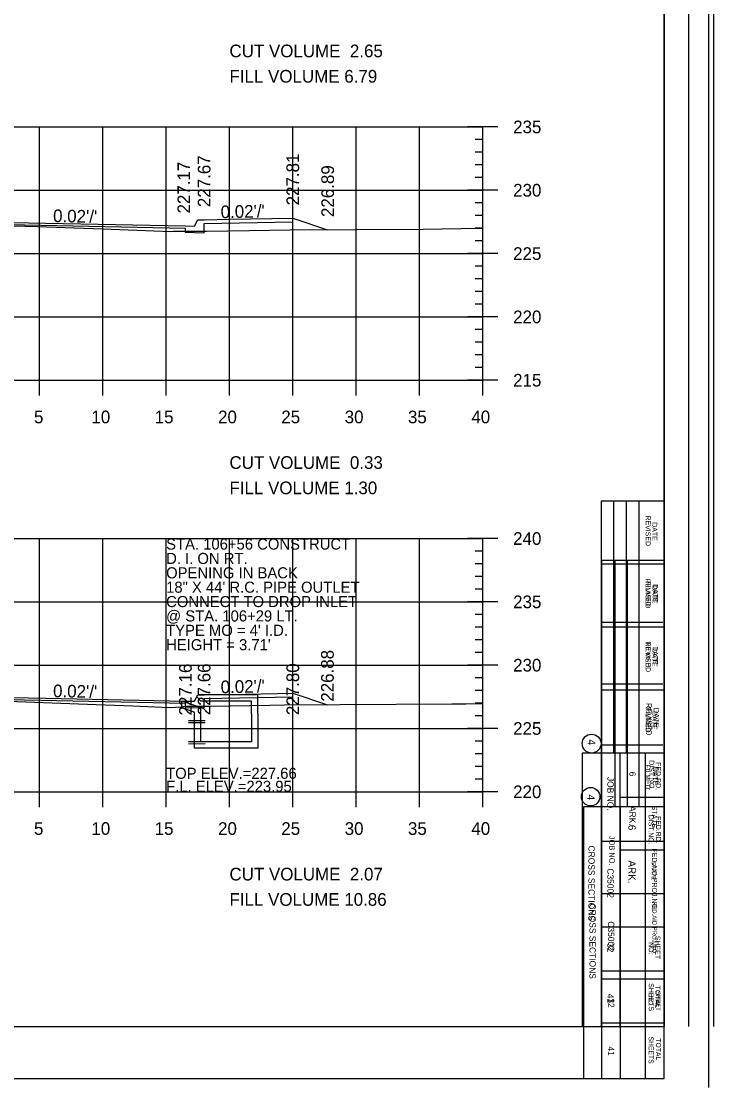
# Model space of a CAD drawing. Extents: x 1367903 to 1373764, y 376865 to 382130.
# Drawn here: x 1371513.6 to 1371623, y 377279.1 to 377447.5 of the extents above; entities that cross this region are included whole.
import ezdxf

# ---------------------------------------------------------------- set-up
doc = ezdxf.new("R2010")
doc.units = 0
for name, color, linetype in [('R_Axis', 7, 'Continuous'), ('R_Axis Annot', 7, 'Continuous'), ('R_Border', 7, 'Continuous'), ('R_Border Notes', 7, 'Continuous'), ('R_Border PE', 7, 'Continuous'), ('R_Draft', 7, 'Continuous'), ('R_Exist Surface', 7, 'Continuous'), ('R_Fin Surface', 7, 'Continuous'), ('R_Fin Surface Annot', 7, 'Continuous'), ('R_Grid', 7, 'Continuous'), ('R_Water', 7, 'Continuous'), ('R_Water Annot', 7, 'Continuous')]:
    doc.layers.add(name, color=color, linetype=linetype)

msp = doc.modelspace()

# ---------------------------------------------------------------- linework, layer by layer
for p, q in [((1371539.01, 377340.19), (1371542.01, 377339.15)), ((1371541.35, 377340.82), (1371541.51, 377341.15)), ((1371541.35, 377340.82), (1371542.01, 377340.15)), ((1371551.01, 377341.15), (1371541.51, 377341.15)), ((1371550.01, 377340.15), (1371542.01, 377340.15)), ((1371550.01, 377338.15), (1371550.01, 377340.15)), ((1371551.01, 377338.15), (1371551.01, 377341.15)), ((1371539.01, 377339.13), (1371541.01, 377338.43)), ((1371541.01, 377338.15), (1371541.01, 377338.43)), ((1371542.01, 377338.15), (1371542.01, 377339.15))]:
    msp.add_line(p, q)
for points in [[(1371470.51, 377416.17), (1371470.51, 377415.5), (1371470.51, 377415.5), (1371470.51, 377414.14), (1371473.51, 377414.2), (1371473.51, 377414.87), (1371506.51, 377415.53), (1371539.51, 377414.87), (1371539.51, 377414.2), (1371542.51, 377414.14), (1371542.51, 377415.58), (1371556.51, 377415.86), (1371556.51, 377416.45)], [(1371470.51, 377341.15), (1371470.51, 377340.48), (1371470.51, 377340.48), (1371470.51, 377339.12), (1371473.51, 377339.18), (1371473.51, 377339.84), (1371506.51, 377340.5), (1371539.51, 377339.84), (1371539.51, 377339.18), (1371542.51, 377339.12), (1371542.51, 377340.56), (1371556.51, 377340.84), (1371556.51, 377341.43)], [(1371539.01, 377339.13), (1371539.01, 377340.19)]]:
    msp.add_lwpolyline(points)
at = {"layer": 'R_Axis'}
for p, q in [((1371588.91, 377430.84), (1371584.11, 377430.84)), ((1371586.51, 377390.84), (1371586.51, 377430.84)), ((1371586.51, 377428.84), (1371585.31, 377428.84)), ((1371586.51, 377426.84), (1371585.31, 377426.84)), ((1371586.51, 377424.84), (1371585.31, 377424.84)), ((1371586.51, 377422.84), (1371585.31, 377422.84)), ((1371588.91, 377420.84), (1371584.11, 377420.84)), ((1371586.51, 377418.84), (1371585.31, 377418.84)), ((1371586.51, 377416.84), (1371585.31, 377416.84)), ((1371586.51, 377414.84), (1371585.31, 377414.84)), ((1371586.51, 377412.84), (1371585.31, 377412.84)), ((1371588.91, 377410.84), (1371584.11, 377410.84)), ((1371586.51, 377408.84), (1371585.31, 377408.84)), ((1371586.51, 377406.84), (1371585.31, 377406.84)), ((1371586.51, 377404.84), (1371585.31, 377404.84)), ((1371586.51, 377402.84), (1371585.31, 377402.84)), ((1371588.91, 377400.84), (1371584.11, 377400.84)), ((1371586.51, 377398.84), (1371585.31, 377398.84)), ((1371586.51, 377396.84), (1371585.31, 377396.84)), ((1371586.51, 377394.84), (1371585.31, 377394.84)), ((1371516.51, 377388.44), (1371516.51, 377393.24)), ((1371526.51, 377388.44), (1371526.51, 377393.24)), ((1371536.51, 377388.44), (1371536.51, 377393.24)), ((1371546.51, 377388.44), (1371546.51, 377393.24)), ((1371556.51, 377388.44), (1371556.51, 377393.24)), ((1371566.51, 377388.44), (1371566.51, 377393.24)), ((1371576.51, 377388.44), (1371576.51, 377393.24)), ((1371586.51, 377392.84), (1371585.31, 377392.84)), ((1371586.51, 377388.44), (1371586.51, 377393.24)), ((1371426.51, 377390.84), (1371586.51, 377390.84)), ((1371588.91, 377390.84), (1371584.11, 377390.84)), ((1371588.91, 377365.84), (1371584.11, 377365.84)), ((1371586.51, 377325.84), (1371586.51, 377365.84)), ((1371586.51, 377363.84), (1371585.31, 377363.84)), ((1371586.51, 377361.84), (1371585.31, 377361.84)), ((1371586.51, 377359.84), (1371585.31, 377359.84)), ((1371586.51, 377357.84), (1371585.31, 377357.84)), ((1371588.91, 377355.84), (1371584.11, 377355.84)), ((1371586.51, 377353.84), (1371585.31, 377353.84)), ((1371586.51, 377351.84), (1371585.31, 377351.84)), ((1371586.51, 377349.84), (1371585.31, 377349.84)), ((1371586.51, 377347.84), (1371585.31, 377347.84)), ((1371588.91, 377345.84), (1371584.11, 377345.84)), ((1371586.51, 377343.84), (1371585.31, 377343.84)), ((1371586.51, 377341.84), (1371585.31, 377341.84)), ((1371586.51, 377339.84), (1371585.31, 377339.84)), ((1371586.51, 377337.84), (1371585.31, 377337.84)), ((1371588.91, 377335.84), (1371584.11, 377335.84)), ((1371586.51, 377333.84), (1371585.31, 377333.84)), ((1371586.51, 377331.84), (1371585.31, 377331.84)), ((1371586.51, 377329.84), (1371585.31, 377329.84)), ((1371516.51, 377323.44), (1371516.51, 377328.24)), ((1371526.51, 377323.44), (1371526.51, 377328.24)), ((1371536.51, 377323.44), (1371536.51, 377328.24)), ((1371546.51, 377323.44), (1371546.51, 377328.24)), ((1371556.51, 377323.44), (1371556.51, 377328.24)), ((1371566.51, 377323.44), (1371566.51, 377328.24)), ((1371576.51, 377323.44), (1371576.51, 377328.24)), ((1371586.51, 377323.44), (1371586.51, 377328.24)), ((1371586.51, 377327.84), (1371585.31, 377327.84)), ((1371426.51, 377325.84), (1371586.51, 377325.84)), ((1371588.91, 377325.84), (1371584.11, 377325.84))]:
    msp.add_line(p, q, dxfattribs=at)
at = {"layer": 'R_Border'}
for p, q in [((1371622.18, 377620.35), (1371622.18, 377279.12)), ((1371615.14, 377280.59), (1371615.14, 377611.47)), ((1371615.14, 377446.03), (1371615.14, 377446.03)), ((1371605.33, 377280.59), (1371605.33, 377362.43)), ((1371605.33, 377362.43), (1371615.14, 377362.43)), ((1371605.33, 377362.43), (1371607.36, 377362.43)), ((1371607.36, 377362.43), (1371607.36, 377323.46)), ((1371609.31, 377362.43), (1371609.31, 377323.46)), ((1371611.16, 377362.43), (1371611.16, 377323.46)), ((1371605.33, 377352.62), (1371614.94, 377352.62)), ((1371605.33, 377342.9), (1371614.94, 377342.9)), ((1371605.33, 377333.27), (1371614.94, 377333.27)), ((1371615.14, 377323.46), (1371602.41, 377323.46)), ((1371602.41, 377323.46), (1371602.41, 377280.59)), ((1371608.24, 377280.59), (1371608.24, 377323.46)), ((1371612.22, 377280.59), (1371612.22, 377323.46)), ((1371615.14, 377316.65), (1371608.24, 377316.65)), ((1371615.14, 377309.75), (1371605.33, 377309.75)), ((1371615.14, 377296.24), (1371605.33, 377296.24)), ((1371615.14, 377289.33), (1371605.33, 377289.33)), ((1371410.82, 377280.59), (1371615.14, 377280.59))]:
    msp.add_line(p, q, dxfattribs=at)
msp.add_circle((1371603.55, 377325.07), 1.46, dxfattribs=at)
at = {"layer": 'R_Border PE'}
for p, q in [((1371619.06, 377288.8), (1371619.06, 377610.76)), ((1371622.98, 377288.8), (1371622.98, 377610.76)), ((1371615.14, 377603.25), (1371615.14, 377288.8)), ((1371605.19, 377371.74), (1371605.19, 377288.8)), ((1371615.14, 377371.74), (1371605.19, 377371.74)), ((1371607.18, 377371.74), (1371607.18, 377331.96)), ((1371609.17, 377371.74), (1371609.17, 377331.96)), ((1371611.16, 377371.74), (1371611.16, 377331.96)), ((1371615.14, 377361.8), (1371605.19, 377361.8)), ((1371615.14, 377351.85), (1371605.19, 377351.85)), ((1371615.14, 377341.91), (1371605.19, 377341.91)), ((1371615.14, 377331.96), (1371602.21, 377331.96)), ((1371602.21, 377331.96), (1371602.21, 377288.8)), ((1371608.18, 377331.96), (1371608.18, 377288.8)), ((1371612.15, 377331.96), (1371612.15, 377288.8)), ((1371608.24, 377325), (1371615.14, 377325)), ((1371605.32, 377318.04), (1371615.14, 377318.04)), ((1371605.32, 377304.51), (1371615.14, 377304.51)), ((1371605.32, 377297.55), (1371615.14, 377297.55)), ((1371410.82, 377288.8), (1371615.14, 377288.8)), ((1371612.25, 377288.8), (1371612.25, 377288.8))]:
    msp.add_line(p, q, dxfattribs=at)
msp.add_circle((1371603.7, 377333.45), 1.49, dxfattribs=at)
at = {"layer": 'R_Exist Surface'}
for points in [[(1371506.64, 377415.36), (1371516.16, 377415.09), (1371522, 377414.89), (1371526.44, 377414.73), (1371531.88, 377414.53), (1371537.27, 377414.34), (1371537.62, 377414.37), (1371539.93, 377414.36), (1371542.88, 377414.37), (1371549.6, 377414.49), (1371556.1, 377414.58), (1371577.12, 377414.7), (1371586.07, 377414.85), (1371586.51, 377414.85)], [(1371508.7, 377340.26), (1371525.47, 377339.64), (1371531.23, 377339.43), (1371537.06, 377339.18), (1371538.95, 377339.28), (1371539.54, 377339.36), (1371541.84, 377339.35), (1371543.45, 377339.36), (1371552.9, 377339.53), (1371555.19, 377339.57), (1371581.63, 377339.72), (1371583.86, 377339.75), (1371586.51, 377339.77)]]:
    msp.add_lwpolyline(points, dxfattribs=at)
at = {"layer": 'R_Fin Surface'}
for points in [[(1371467.84, 377415.28), (1371470.51, 377416.17), (1371471.51, 377416.17), (1371472.01, 377415.17), (1371473.51, 377415.2), (1371495.51, 377415.64), (1371506.51, 377415.86), (1371517.51, 377415.64), (1371539.51, 377415.2), (1371541.01, 377415.17), (1371541.51, 377416.17), (1371542.51, 377416.17), (1371546.51, 377416.25), (1371556.51, 377416.45), (1371562.02, 377414.61)], [(1371467.79, 377340.24), (1371470.51, 377341.15), (1371471.51, 377341.15), (1371472.01, 377340.15), (1371473.51, 377340.18), (1371495.51, 377340.62), (1371506.51, 377340.84), (1371517.51, 377340.62), (1371539.51, 377340.18), (1371541.01, 377340.15), (1371541.51, 377341.15), (1371542.51, 377341.15), (1371546.51, 377341.23), (1371556.51, 377341.43), (1371561.98, 377339.6)]]:
    msp.add_lwpolyline(points, dxfattribs=at)
at = {"layer": 'R_Grid'}
for p, q in [((1371426.51, 377430.84), (1371586.51, 377430.84)), ((1371516.51, 377390.84), (1371516.51, 377430.84)), ((1371526.51, 377390.84), (1371526.51, 377430.84)), ((1371536.51, 377390.84), (1371536.51, 377430.84)), ((1371546.51, 377390.84), (1371546.51, 377430.84)), ((1371556.51, 377390.84), (1371556.51, 377430.84)), ((1371566.51, 377390.84), (1371566.51, 377430.84)), ((1371576.51, 377390.84), (1371576.51, 377430.84)), ((1371586.51, 377390.84), (1371586.51, 377430.84)), ((1371426.51, 377420.84), (1371586.51, 377420.84)), ((1371426.51, 377410.84), (1371586.51, 377410.84)), ((1371426.51, 377400.84), (1371586.51, 377400.84)), ((1371426.51, 377390.84), (1371586.51, 377390.84)), ((1371426.51, 377365.84), (1371586.51, 377365.84)), ((1371516.51, 377325.84), (1371516.51, 377365.84)), ((1371526.51, 377325.84), (1371526.51, 377365.84)), ((1371536.51, 377325.84), (1371536.51, 377365.84)), ((1371546.51, 377325.84), (1371546.51, 377365.84)), ((1371556.51, 377325.84), (1371556.51, 377365.84)), ((1371566.51, 377325.84), (1371566.51, 377365.84)), ((1371576.51, 377325.84), (1371576.51, 377365.84)), ((1371586.51, 377325.84), (1371586.51, 377365.84)), ((1371426.51, 377355.84), (1371586.51, 377355.84)), ((1371426.51, 377345.84), (1371586.51, 377345.84)), ((1371426.51, 377335.84), (1371586.51, 377335.84)), ((1371426.51, 377325.84), (1371586.51, 377325.84))]:
    msp.add_line(p, q, dxfattribs=at)
at = {"layer": 'R_Water'}
for p, q in [((1371542.69, 377337.07), (1371540.04, 377337.05)), ((1371542.69, 377336.74), (1371540.04, 377336.72)), ((1371542.69, 377333.74), (1371540.04, 377333.72)), ((1371542.69, 377333.4), (1371540.04, 377333.39))]:
    msp.add_line(p, q, dxfattribs=at)
for points in [[(1371551.01, 377338.15), (1371551.01, 377332.74), (1371546.01, 377332.74), (1371541.01, 377332.74), (1371541.01, 377338.15)], [(1371550.01, 377338.15), (1371550.01, 377333.74), (1371546.01, 377333.74), (1371542.01, 377333.74), (1371542.01, 377338.15)]]:
    msp.add_lwpolyline(points, dxfattribs=at)

# ---------------------------------------------------------------- texts
at = {"layer": 'R_Axis Annot'}
for s, p in [('CUT VOLUME  2.65', (1371546.51, 377441.84)), ('FILL VOLUME 6.79', (1371546.51, 377437.84)), ('235', (1371591.31, 377429.84)), ('230', (1371591.31, 377419.84)), ('225', (1371591.31, 377409.84)), ('220', (1371591.31, 377399.84)), ('215', (1371591.31, 377389.84)), ('5', (1371515.64, 377384.04)), ('10', (1371524.71, 377384.04)), ('15', (1371534.7, 377384.04)), ('20', (1371544.71, 377384.04)), ('25', (1371554.7, 377384.04)), ('30', (1371564.71, 377384.04)), ('35', (1371574.7, 377384.04)), ('40', (1371584.71, 377384.04)), ('CUT VOLUME  0.33', (1371546.51, 377376.84)), ('FILL VOLUME 1.30', (1371546.51, 377372.84)), ('240', (1371591.31, 377364.84)), ('235', (1371591.31, 377354.84)), ('230', (1371591.31, 377344.84)), ('225', (1371591.31, 377334.84)), ('220', (1371591.31, 377324.84)), ('5', (1371515.64, 377319.04)), ('10', (1371524.71, 377319.04)), ('15', (1371534.7, 377319.04)), ('20', (1371544.71, 377319.04)), ('25', (1371554.7, 377319.04)), ('30', (1371564.71, 377319.04)), ('35', (1371574.7, 377319.04)), ('40', (1371584.71, 377319.04)), ('CUT VOLUME  2.07', (1371546.51, 377311.84)), ('FILL VOLUME 10.86', (1371546.51, 377307.84))]:
    msp.add_text(s, height=2, dxfattribs=at).set_placement(p)
at = {"layer": 'R_Border'}
for s, height, p in [('REVISED', 0.778, (1371612.22, 377359.51)), ('DATE', 0.778, (1371613.39, 377358.64)), ('FILMED', 0.778, (1371612.22, 377349.41)), ('DATE', 0.778, (1371613.39, 377348.82)), ('REVISED', 0.875, (1371612.32, 377339.88)), ('DATE', 0.875, (1371613.49, 377339.1)), ('FILMED', 0.778, (1371612.22, 377330.16)), ('DATE', 0.778, (1371613.39, 377329.77)), ('4', 1.17, (1371603.03, 377325.4)), ('DIST.NO.', 0.778, (1371612.71, 377322.19)), ('FED.RD.', 0.778, (1371613.88, 377321.99)), ('6', 1.17, (1371609.5, 377320.63)), ('JOB NO.', 0.875, (1371606.49, 377318.88)), ('ARK.', 1.166, (1371609.5, 377315)), ('STATE', 0.681, (1371613.19, 377314.9)), ('FED.AID PROJ.NO.', 0.6805, (1371613.3, 377308.49)), ('NO.', 0.681, (1371612.71, 377293.61)), ('SHEET', 0.681, (1371613.88, 377294.39)), ('SHEETS', 0.778, (1371612.71, 377287.2)), ('TOTAL', 0.778, (1371613.88, 377286.91))]:
    msp.add_text(s, height=height, rotation=270, dxfattribs=at).set_placement(p)
at = {"layer": 'R_Border Notes'}
for s, height, p in [('CROSS SECTIONS', 0.9945, (1371603.37, 377308.2)), ('C35002', 0.995, (1371606.29, 377305.39)), ('32', 0.995, (1371606.29, 377293.23)), ('41', 0.995, (1371606.29, 377285.62))]:
    msp.add_text(s, height=height, rotation=270, dxfattribs=at).set_placement(p)
at = {"layer": 'R_Border PE'}
for s, height, p in [('REVISED', 0.796, (1371612.24, 377369.47)), ('DATE', 0.796, (1371613.27, 377368.41)), ('FILMED', 0.796, (1371612.24, 377359.12)), ('DATE', 0.796, (1371613.27, 377358.47)), ('REVISED', 0.796, (1371612.24, 377349.57)), ('DATE', 0.796, (1371613.27, 377348.52)), ('FILMED', 0.796, (1371612.24, 377339.23)), ('DATE', 0.796, (1371613.27, 377338.58)), ('4', 1.19, (1371603.1, 377334.12)), ('DIST.NO.', 0.796, (1371612.81, 377330.83)), ('FED.RD.', 0.796, (1371613.84, 377330.52)), ('JOB NO.', 0.995, (1371606.19, 377328.19)), ('6', 0.995, (1371609.67, 377329.02)), ('ARK.', 0.995, (1371609.67, 377323.6)), ('STATE', 0.796, (1371613.25, 377323.66)), ('CROSS SECTIONS', 0.9945, (1371603.2, 377317.35)), ('FED.AID PROJ.NO.', 0.7956, (1371613.25, 377316.88)), ('C35002', 0.995, (1371606.19, 377313.75)), ('SHEET', 0.796, (1371613.76, 377303.09)), ('32', 0.995, (1371606.19, 377301.96)), ('NO.', 0.796, (1371612.73, 377302.11)), ('SHEETS', 0.796, (1371612.73, 377295.62)), ('TOTAL', 0.796, (1371613.76, 377295.23)), ('41', 0.995, (1371606.19, 377293.96))]:
    msp.add_text(s, height=height, rotation=270, dxfattribs=at).set_placement(p)
at = {"layer": 'R_Draft'}
for s, p in [('STA. 106+56 CONSTRUCT', (1371536.51, 377364.09)), ('D. I. ON RT.', (1371536.51, 377361.82)), ('OPENING IN BACK', (1371536.51, 377359.55)), ('18" X 44\' R.C. PIPE OUTLET', (1371536.51, 377357.28)), ('CONNECT TO DROP INLET', (1371536.51, 377355.01)), ('@ STA. 106+29 LT.', (1371536.51, 377352.74)), ("TYPE MO = 4' I.D.", (1371536.51, 377350.47)), ("HEIGHT = 3.71'", (1371536.51, 377348.2))]:
    msp.add_text(s, height=1.75, dxfattribs=at).set_placement(p)
at = {"layer": 'R_Fin Surface Annot'}
for s, rotation, p in [('227.67', 90, (1371543.51, 377418.17)), ('227.81', 90, (1371557.51, 377418.45)), ('227.17', 90, (1371540.3, 377417.17)), ('226.89', 90, (1371563.02, 377416.61)), ("0.02'/'", 358.8541, (1371518.64, 377415.82)), ("0.02'/'", 1.1456, (1371545.14, 377416.42)), ('226.88', 90, (1371562.98, 377340.07)), ('227.16', 90, (1371540.55, 377337.9)), ('227.66', 90, (1371543.51, 377337.93)), ('227.80', 90, (1371557.51, 377337.95)), ("0.02'/'", 1.1457, (1371545.14, 377341.4)), ("0.02'/'", 358.8541, (1371518.64, 377340.79))]:
    msp.add_text(s, height=2, rotation=rotation, dxfattribs=at).set_placement(p)
at = {"layer": 'R_Water Annot'}
for s, p in [('TOP ELEV.=227.66', (1371536.51, 377327.89)), ('F.L. ELEV.=223.95', (1371536.51, 377325.84))]:
    msp.add_text(s, height=1.75, dxfattribs=at).set_placement(p)

doc.saveas('drawing.dxf')
